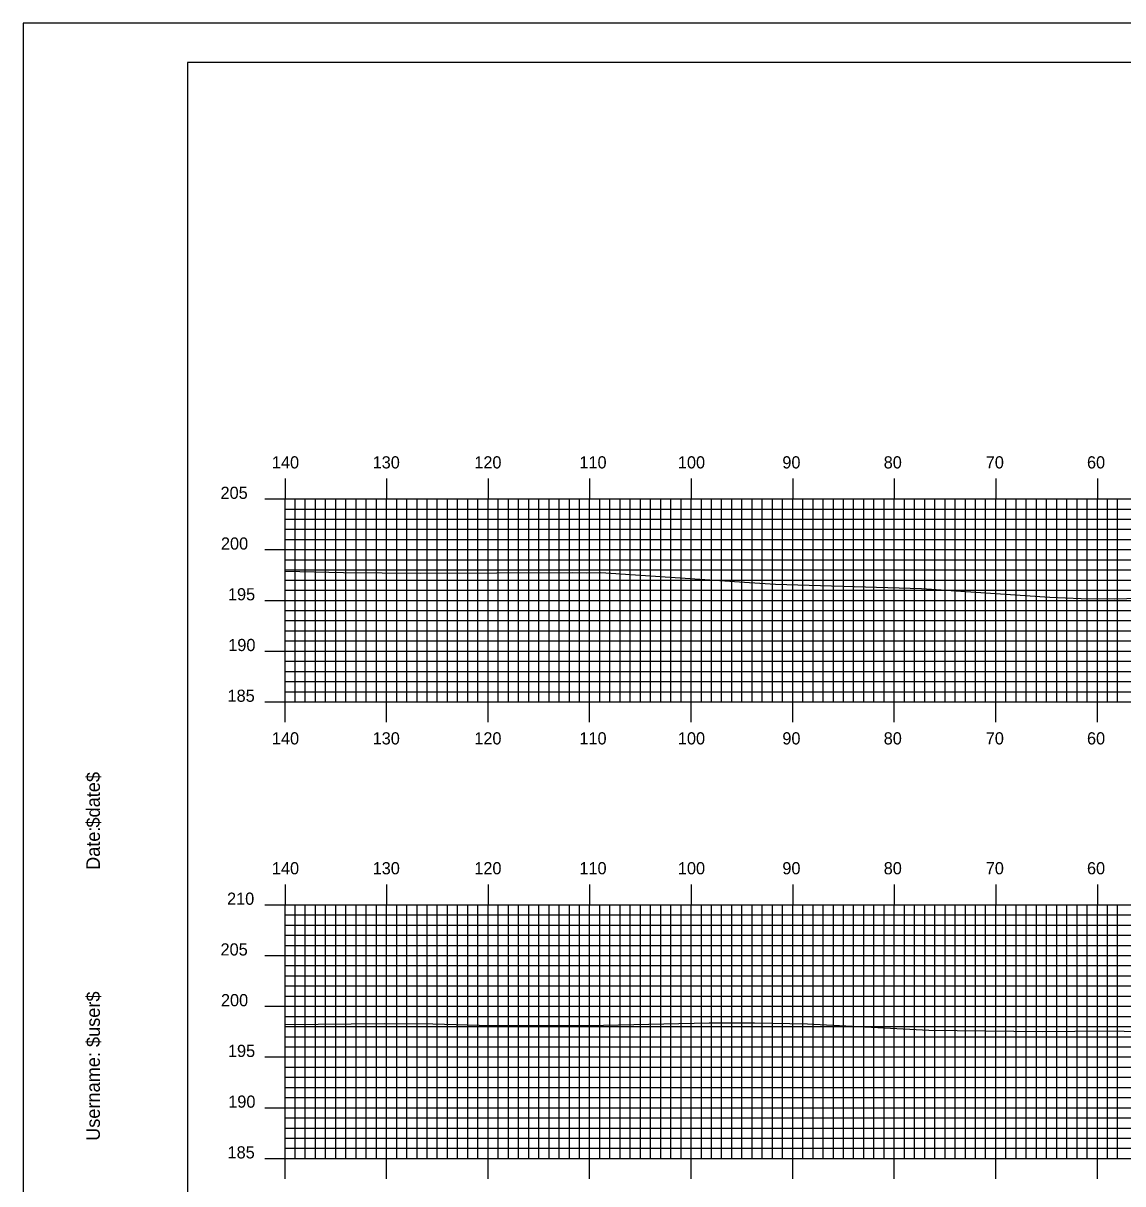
# Model space of a CAD drawing. Extents: x 1814128 to 1814471, y 442591 to 442811.
# Drawn here: x 1814128.2 to 1814236.5, y 442696.2 to 442810.5 of the extents above; entities that cross this region are included whole.
import ezdxf

# ---------------------------------------------------------------- set-up
doc = ezdxf.new("R2010")
doc.units = 0
for name, color, linetype in [('BORDER', 7, 'Continuous'), ('H_V ANNOTATION', 7, 'Continuous'), ('MAJOR', 7, 'Continuous'), ('MINOR', 7, 'Continuous'), ('PLOT BOUNDARY', 7, 'Continuous'), ('S_Roadway_Centerline', 7, 'Continuous')]:
    doc.layers.add(name, color=color, linetype=linetype)

msp = doc.modelspace()

# ---------------------------------------------------------------- linework, layer by layer
at = {"layer": 'BORDER'}
msp.add_lwpolyline([(1814144.39, 442596.67), (1814464.39, 442596.67), (1814464.39, 442806.67), (1814144.39, 442806.67)], close=True, dxfattribs=at)
at = {"layer": 'MAJOR'}
for p, q in [((1814153.99, 442765.67), (1814153.99, 442763.67)), ((1814163.99, 442765.67), (1814163.99, 442763.67)), ((1814173.99, 442765.67), (1814173.99, 442763.67)), ((1814183.99, 442765.67), (1814183.99, 442763.67)), ((1814193.99, 442765.67), (1814193.99, 442763.67)), ((1814203.99, 442765.67), (1814203.99, 442763.67)), ((1814213.99, 442765.67), (1814213.99, 442763.67)), ((1814223.99, 442765.67), (1814223.99, 442763.67)), ((1814233.99, 442765.67), (1814233.99, 442763.67)), ((1814151.99, 442763.67), (1814153.99, 442763.67)), ((1814153.99, 442763.67), (1814433.99, 442763.67)), ((1814153.99, 442743.67), (1814153.99, 442763.67)), ((1814153.99, 442743.67), (1814153.99, 442763.67)), ((1814153.99, 442763.67), (1814433.99, 442763.67)), ((1814163.99, 442743.67), (1814163.99, 442763.67)), ((1814173.99, 442743.67), (1814173.99, 442763.67)), ((1814183.99, 442743.67), (1814183.99, 442763.67)), ((1814193.99, 442743.67), (1814193.99, 442763.67)), ((1814203.99, 442743.67), (1814203.99, 442763.67)), ((1814213.99, 442743.67), (1814213.99, 442763.67)), ((1814223.99, 442743.67), (1814223.99, 442763.67)), ((1814233.99, 442743.67), (1814233.99, 442763.67)), ((1814151.99, 442758.67), (1814153.99, 442758.67)), ((1814153.99, 442758.67), (1814433.99, 442758.67)), ((1814151.99, 442753.67), (1814153.99, 442753.67)), ((1814153.99, 442753.67), (1814433.99, 442753.67)), ((1814151.99, 442748.67), (1814153.99, 442748.67)), ((1814153.99, 442748.67), (1814433.99, 442748.67)), ((1814151.99, 442743.67), (1814153.99, 442743.67)), ((1814153.99, 442743.67), (1814433.99, 442743.67)), ((1814153.99, 442743.67), (1814433.99, 442743.67)), ((1814153.99, 442741.66), (1814153.99, 442743.67)), ((1814163.99, 442741.66), (1814163.99, 442743.67)), ((1814173.99, 442741.66), (1814173.99, 442743.67)), ((1814183.99, 442741.66), (1814183.99, 442743.67)), ((1814193.99, 442741.66), (1814193.99, 442743.67)), ((1814203.99, 442741.66), (1814203.99, 442743.67)), ((1814213.99, 442741.66), (1814213.99, 442743.67)), ((1814223.99, 442741.66), (1814223.99, 442743.67)), ((1814233.99, 442741.66), (1814233.99, 442743.67)), ((1814153.99, 442725.67), (1814153.99, 442723.67)), ((1814163.99, 442725.67), (1814163.99, 442723.67)), ((1814173.99, 442725.67), (1814173.99, 442723.67)), ((1814183.99, 442725.67), (1814183.99, 442723.67)), ((1814193.99, 442725.67), (1814193.99, 442723.67)), ((1814203.99, 442725.67), (1814203.99, 442723.67)), ((1814213.99, 442725.67), (1814213.99, 442723.67)), ((1814223.99, 442725.67), (1814223.99, 442723.67)), ((1814233.99, 442725.67), (1814233.99, 442723.67)), ((1814151.99, 442723.67), (1814153.99, 442723.67)), ((1814153.99, 442723.67), (1814433.99, 442723.67)), ((1814153.99, 442698.67), (1814153.99, 442723.67)), ((1814153.99, 442698.67), (1814153.99, 442723.67)), ((1814153.99, 442723.67), (1814433.99, 442723.67)), ((1814163.99, 442698.67), (1814163.99, 442723.67)), ((1814173.99, 442698.67), (1814173.99, 442723.67)), ((1814183.99, 442698.67), (1814183.99, 442723.67)), ((1814193.99, 442698.67), (1814193.99, 442723.67)), ((1814203.99, 442698.67), (1814203.99, 442723.67)), ((1814213.99, 442698.67), (1814213.99, 442723.67)), ((1814223.99, 442698.67), (1814223.99, 442723.67)), ((1814233.99, 442698.67), (1814233.99, 442723.67)), ((1814151.99, 442718.67), (1814153.99, 442718.67)), ((1814153.99, 442718.67), (1814433.99, 442718.67)), ((1814151.99, 442713.67), (1814153.99, 442713.67)), ((1814153.99, 442713.67), (1814433.99, 442713.67)), ((1814151.99, 442708.67), (1814153.99, 442708.67)), ((1814153.99, 442708.67), (1814433.99, 442708.67)), ((1814151.99, 442703.67), (1814153.99, 442703.67)), ((1814153.99, 442703.67), (1814433.99, 442703.67)), ((1814151.99, 442698.67), (1814153.99, 442698.67)), ((1814153.99, 442698.67), (1814433.99, 442698.67)), ((1814153.99, 442698.67), (1814433.99, 442698.67)), ((1814153.99, 442696.66), (1814153.99, 442698.67)), ((1814163.99, 442696.66), (1814163.99, 442698.67)), ((1814173.99, 442696.66), (1814173.99, 442698.67)), ((1814183.99, 442696.66), (1814183.99, 442698.67)), ((1814193.99, 442696.66), (1814193.99, 442698.67)), ((1814203.99, 442696.66), (1814203.99, 442698.67)), ((1814213.99, 442696.66), (1814213.99, 442698.67)), ((1814223.99, 442696.66), (1814223.99, 442698.67)), ((1814233.99, 442696.66), (1814233.99, 442698.67))]:
    msp.add_line(p, q, dxfattribs=at)
at = {"layer": 'MINOR'}
for p, q in [((1814154.99, 442743.67), (1814154.99, 442763.67)), ((1814155.99, 442743.67), (1814155.99, 442763.67)), ((1814156.99, 442743.67), (1814156.99, 442763.67)), ((1814157.99, 442743.67), (1814157.99, 442763.67)), ((1814158.99, 442743.67), (1814158.99, 442763.67)), ((1814159.99, 442743.67), (1814159.99, 442763.67)), ((1814160.99, 442743.67), (1814160.99, 442763.67)), ((1814161.99, 442743.67), (1814161.99, 442763.67)), ((1814162.99, 442743.67), (1814162.99, 442763.67)), ((1814164.99, 442743.67), (1814164.99, 442763.67)), ((1814165.99, 442743.67), (1814165.99, 442763.67)), ((1814166.99, 442743.67), (1814166.99, 442763.67)), ((1814167.99, 442743.67), (1814167.99, 442763.67)), ((1814168.99, 442743.67), (1814168.99, 442763.67)), ((1814169.99, 442743.67), (1814169.99, 442763.67)), ((1814170.99, 442743.67), (1814170.99, 442763.67)), ((1814171.99, 442743.67), (1814171.99, 442763.67)), ((1814172.99, 442743.67), (1814172.99, 442763.67)), ((1814174.99, 442743.67), (1814174.99, 442763.67)), ((1814175.99, 442743.67), (1814175.99, 442763.67)), ((1814176.99, 442743.67), (1814176.99, 442763.67)), ((1814177.99, 442743.67), (1814177.99, 442763.67)), ((1814178.99, 442743.67), (1814178.99, 442763.67)), ((1814179.99, 442743.67), (1814179.99, 442763.67)), ((1814180.99, 442743.67), (1814180.99, 442763.67)), ((1814181.99, 442743.67), (1814181.99, 442763.67)), ((1814182.99, 442743.67), (1814182.99, 442763.67)), ((1814184.99, 442743.67), (1814184.99, 442763.67)), ((1814185.99, 442743.67), (1814185.99, 442763.67)), ((1814186.99, 442743.67), (1814186.99, 442763.67)), ((1814187.99, 442743.67), (1814187.99, 442763.67)), ((1814188.99, 442743.67), (1814188.99, 442763.67)), ((1814189.99, 442743.67), (1814189.99, 442763.67)), ((1814190.99, 442743.67), (1814190.99, 442763.67)), ((1814191.99, 442743.67), (1814191.99, 442763.67)), ((1814192.99, 442743.67), (1814192.99, 442763.67)), ((1814194.99, 442743.67), (1814194.99, 442763.67)), ((1814195.99, 442743.67), (1814195.99, 442763.67)), ((1814196.99, 442743.67), (1814196.99, 442763.67)), ((1814197.99, 442743.67), (1814197.99, 442763.67)), ((1814198.99, 442743.67), (1814198.99, 442763.67)), ((1814199.99, 442743.67), (1814199.99, 442763.67)), ((1814200.99, 442743.67), (1814200.99, 442763.67)), ((1814201.99, 442743.67), (1814201.99, 442763.67)), ((1814202.99, 442743.67), (1814202.99, 442763.67)), ((1814204.99, 442743.67), (1814204.99, 442763.67)), ((1814205.99, 442743.67), (1814205.99, 442763.67)), ((1814206.99, 442743.67), (1814206.99, 442763.67)), ((1814207.99, 442743.67), (1814207.99, 442763.67)), ((1814208.99, 442743.67), (1814208.99, 442763.67)), ((1814209.99, 442743.67), (1814209.99, 442763.67)), ((1814210.99, 442743.67), (1814210.99, 442763.67)), ((1814211.99, 442743.67), (1814211.99, 442763.67)), ((1814212.99, 442743.67), (1814212.99, 442763.67)), ((1814214.99, 442743.67), (1814214.99, 442763.67)), ((1814215.99, 442743.67), (1814215.99, 442763.67)), ((1814216.99, 442743.67), (1814216.99, 442763.67)), ((1814217.99, 442743.67), (1814217.99, 442763.67)), ((1814218.99, 442743.67), (1814218.99, 442763.67)), ((1814219.99, 442743.67), (1814219.99, 442763.67)), ((1814220.99, 442743.67), (1814220.99, 442763.67)), ((1814221.99, 442743.67), (1814221.99, 442763.67)), ((1814222.99, 442743.67), (1814222.99, 442763.67)), ((1814224.99, 442743.67), (1814224.99, 442763.67)), ((1814225.99, 442743.67), (1814225.99, 442763.67)), ((1814226.99, 442743.67), (1814226.99, 442763.67)), ((1814227.99, 442743.67), (1814227.99, 442763.67)), ((1814228.99, 442743.67), (1814228.99, 442763.67)), ((1814229.99, 442743.67), (1814229.99, 442763.67)), ((1814230.99, 442743.67), (1814230.99, 442763.67)), ((1814231.99, 442743.67), (1814231.99, 442763.67)), ((1814232.99, 442743.67), (1814232.99, 442763.67)), ((1814234.99, 442743.67), (1814234.99, 442763.67)), ((1814235.99, 442743.67), (1814235.99, 442763.67)), ((1814153.99, 442762.67), (1814433.99, 442762.67)), ((1814153.99, 442762.67), (1814156, 442762.67)), ((1814153.99, 442761.67), (1814433.99, 442761.67)), ((1814153.99, 442761.67), (1814156, 442761.67)), ((1814153.99, 442760.67), (1814433.99, 442760.67)), ((1814153.99, 442760.67), (1814156, 442760.67)), ((1814153.99, 442759.67), (1814433.99, 442759.67)), ((1814153.99, 442759.67), (1814156, 442759.67)), ((1814153.99, 442757.67), (1814433.99, 442757.67)), ((1814153.99, 442757.67), (1814156, 442757.67)), ((1814153.99, 442756.67), (1814433.99, 442756.67)), ((1814153.99, 442756.67), (1814156, 442756.67)), ((1814153.99, 442755.67), (1814433.99, 442755.67)), ((1814153.99, 442755.67), (1814156, 442755.67)), ((1814153.99, 442754.67), (1814433.99, 442754.67)), ((1814153.99, 442754.67), (1814156, 442754.67)), ((1814153.99, 442752.67), (1814433.99, 442752.67)), ((1814153.99, 442752.67), (1814156, 442752.67)), ((1814153.99, 442751.67), (1814433.99, 442751.67)), ((1814153.99, 442751.67), (1814156, 442751.67)), ((1814153.99, 442750.67), (1814433.99, 442750.67)), ((1814153.99, 442750.67), (1814156, 442750.67)), ((1814153.99, 442749.67), (1814433.99, 442749.67)), ((1814153.99, 442749.67), (1814156, 442749.67)), ((1814153.99, 442747.67), (1814433.99, 442747.67)), ((1814153.99, 442747.67), (1814156, 442747.67)), ((1814153.99, 442746.67), (1814433.99, 442746.67)), ((1814153.99, 442746.67), (1814156, 442746.67)), ((1814153.99, 442745.67), (1814433.99, 442745.67)), ((1814153.99, 442745.67), (1814156, 442745.67)), ((1814153.99, 442744.67), (1814433.99, 442744.67)), ((1814153.99, 442744.67), (1814156, 442744.67)), ((1814154.99, 442698.67), (1814154.99, 442723.67)), ((1814155.99, 442698.67), (1814155.99, 442723.67)), ((1814156.99, 442698.67), (1814156.99, 442723.67)), ((1814157.99, 442698.67), (1814157.99, 442723.67)), ((1814158.99, 442698.67), (1814158.99, 442723.67)), ((1814159.99, 442698.67), (1814159.99, 442723.67)), ((1814160.99, 442698.67), (1814160.99, 442723.67)), ((1814161.99, 442698.67), (1814161.99, 442723.67)), ((1814162.99, 442698.67), (1814162.99, 442723.67)), ((1814164.99, 442698.67), (1814164.99, 442723.67)), ((1814165.99, 442698.67), (1814165.99, 442723.67)), ((1814166.99, 442698.67), (1814166.99, 442723.67)), ((1814167.99, 442698.67), (1814167.99, 442723.67)), ((1814168.99, 442698.67), (1814168.99, 442723.67)), ((1814169.99, 442698.67), (1814169.99, 442723.67)), ((1814170.99, 442698.67), (1814170.99, 442723.67)), ((1814171.99, 442698.67), (1814171.99, 442723.67)), ((1814172.99, 442698.67), (1814172.99, 442723.67)), ((1814174.99, 442698.67), (1814174.99, 442723.67)), ((1814175.99, 442698.67), (1814175.99, 442723.67)), ((1814176.99, 442698.67), (1814176.99, 442723.67)), ((1814177.99, 442698.67), (1814177.99, 442723.67)), ((1814178.99, 442698.67), (1814178.99, 442723.67)), ((1814179.99, 442698.67), (1814179.99, 442723.67)), ((1814180.99, 442698.67), (1814180.99, 442723.67)), ((1814181.99, 442698.67), (1814181.99, 442723.67)), ((1814182.99, 442698.67), (1814182.99, 442723.67)), ((1814184.99, 442698.67), (1814184.99, 442723.67)), ((1814185.99, 442698.67), (1814185.99, 442723.67)), ((1814186.99, 442698.67), (1814186.99, 442723.67)), ((1814187.99, 442698.67), (1814187.99, 442723.67)), ((1814188.99, 442698.67), (1814188.99, 442723.67)), ((1814189.99, 442698.67), (1814189.99, 442723.67)), ((1814190.99, 442698.67), (1814190.99, 442723.67)), ((1814191.99, 442698.67), (1814191.99, 442723.67)), ((1814192.99, 442698.67), (1814192.99, 442723.67)), ((1814194.99, 442698.67), (1814194.99, 442723.67)), ((1814195.99, 442698.67), (1814195.99, 442723.67)), ((1814196.99, 442698.67), (1814196.99, 442723.67)), ((1814197.99, 442698.67), (1814197.99, 442723.67)), ((1814198.99, 442698.67), (1814198.99, 442723.67)), ((1814199.99, 442698.67), (1814199.99, 442723.67)), ((1814200.99, 442698.67), (1814200.99, 442723.67)), ((1814201.99, 442698.67), (1814201.99, 442723.67)), ((1814202.99, 442698.67), (1814202.99, 442723.67)), ((1814204.99, 442698.67), (1814204.99, 442723.67)), ((1814205.99, 442698.67), (1814205.99, 442723.67)), ((1814206.99, 442698.67), (1814206.99, 442723.67)), ((1814207.99, 442698.67), (1814207.99, 442723.67)), ((1814208.99, 442698.67), (1814208.99, 442723.67)), ((1814209.99, 442698.67), (1814209.99, 442723.67)), ((1814210.99, 442698.67), (1814210.99, 442723.67)), ((1814211.99, 442698.67), (1814211.99, 442723.67)), ((1814212.99, 442698.67), (1814212.99, 442723.67)), ((1814214.99, 442698.67), (1814214.99, 442723.67)), ((1814215.99, 442698.67), (1814215.99, 442723.67)), ((1814216.99, 442698.67), (1814216.99, 442723.67)), ((1814217.99, 442698.67), (1814217.99, 442723.67)), ((1814218.99, 442698.67), (1814218.99, 442723.67)), ((1814219.99, 442698.67), (1814219.99, 442723.67)), ((1814220.99, 442698.67), (1814220.99, 442723.67)), ((1814221.99, 442698.67), (1814221.99, 442723.67)), ((1814222.99, 442698.67), (1814222.99, 442723.67)), ((1814224.99, 442698.67), (1814224.99, 442723.67)), ((1814225.99, 442698.67), (1814225.99, 442723.67)), ((1814226.99, 442698.67), (1814226.99, 442723.67)), ((1814227.99, 442698.67), (1814227.99, 442723.67)), ((1814228.99, 442698.67), (1814228.99, 442723.67)), ((1814229.99, 442698.67), (1814229.99, 442723.67)), ((1814230.99, 442698.67), (1814230.99, 442723.67)), ((1814231.99, 442698.67), (1814231.99, 442723.67)), ((1814232.99, 442698.67), (1814232.99, 442723.67)), ((1814234.99, 442698.67), (1814234.99, 442723.67)), ((1814235.99, 442698.67), (1814235.99, 442723.67)), ((1814153.99, 442722.67), (1814433.99, 442722.67)), ((1814153.99, 442722.67), (1814156, 442722.67)), ((1814153.99, 442721.67), (1814433.99, 442721.67)), ((1814153.99, 442721.67), (1814156, 442721.67)), ((1814153.99, 442720.67), (1814433.99, 442720.67)), ((1814153.99, 442720.67), (1814156, 442720.67)), ((1814153.99, 442719.67), (1814433.99, 442719.67)), ((1814153.99, 442719.67), (1814156, 442719.67)), ((1814153.99, 442717.67), (1814433.99, 442717.67)), ((1814153.99, 442717.67), (1814156, 442717.67)), ((1814153.99, 442716.67), (1814433.99, 442716.67)), ((1814153.99, 442716.67), (1814156, 442716.67)), ((1814153.99, 442715.67), (1814433.99, 442715.67)), ((1814153.99, 442715.67), (1814156, 442715.67)), ((1814153.99, 442714.67), (1814433.99, 442714.67)), ((1814153.99, 442714.67), (1814156, 442714.67)), ((1814153.99, 442712.67), (1814433.99, 442712.67)), ((1814153.99, 442712.67), (1814156, 442712.67)), ((1814153.99, 442711.67), (1814433.99, 442711.67)), ((1814153.99, 442711.67), (1814156, 442711.67)), ((1814153.99, 442710.67), (1814433.99, 442710.67)), ((1814153.99, 442710.67), (1814156, 442710.67)), ((1814153.99, 442709.67), (1814433.99, 442709.67)), ((1814153.99, 442709.67), (1814156, 442709.67)), ((1814153.99, 442707.67), (1814433.99, 442707.67)), ((1814153.99, 442707.67), (1814156, 442707.67)), ((1814153.99, 442706.67), (1814433.99, 442706.67)), ((1814153.99, 442706.67), (1814156, 442706.67)), ((1814153.99, 442705.67), (1814433.99, 442705.67)), ((1814153.99, 442705.67), (1814156, 442705.67)), ((1814153.99, 442704.67), (1814433.99, 442704.67)), ((1814153.99, 442704.67), (1814156, 442704.67)), ((1814153.99, 442702.67), (1814433.99, 442702.67)), ((1814153.99, 442702.67), (1814156, 442702.67)), ((1814153.99, 442701.67), (1814433.99, 442701.67)), ((1814153.99, 442701.67), (1814156, 442701.67)), ((1814153.99, 442700.67), (1814433.99, 442700.67)), ((1814153.99, 442700.67), (1814156, 442700.67)), ((1814153.99, 442699.67), (1814433.99, 442699.67)), ((1814153.99, 442699.67), (1814156, 442699.67))]:
    msp.add_line(p, q, dxfattribs=at)
at = {"layer": 'PLOT BOUNDARY'}
msp.add_lwpolyline([(1814128.21, 442590.55), (1814468.21, 442590.55), (1814468.21, 442810.55), (1814128.21, 442810.55)], close=True, dxfattribs=at)
at = {"layer": 'S_Roadway_Centerline'}
for points in [[(1814153.99, 442756.55), (1814159.74, 442756.4), (1814167.36, 442756.36), (1814182.33, 442756.41), (1814183.68, 442756.38), (1814185.1, 442756.41), (1814199.73, 442755.43), (1814202.3, 442755.27), (1814216.68, 442754.85), (1814229.31, 442753.99), (1814232.4, 442753.86), (1814235.66, 442753.82), (1814249.38, 442754.17)], [(1814153.99, 442711.86), (1814163.74, 442711.96), (1814168.55, 442711.95), (1814174.26, 442711.78), (1814185.34, 442711.81), (1814195.77, 442712.03), (1814200.21, 442712.02), (1814205.46, 442711.93), (1814217.38, 442711.3), (1814228.57, 442711.18), (1814234.98, 442711.24), (1814239.96, 442711.14)]]:
    msp.add_lwpolyline(points, dxfattribs=at)

# ---------------------------------------------------------------- texts
at = {"layer": 'BORDER'}
for s, p in [('$date$', (1814135.76, 442731.28)), ('Date:', (1814135.76, 442727.1)), ('$user$', (1814135.76, 442709.65)), ('Username:', (1814135.76, 442700.4))]:
    msp.add_text(s, height=1.339, rotation=90, dxfattribs=at).set_placement(p)
at = {"layer": 'H_V ANNOTATION'}
for s, p in [('140', (1814152.7, 442766.67)), ('130', (1814162.62, 442766.67)), ('120', (1814172.63, 442766.67)), ('110', (1814182.98, 442766.67)), ('100', (1814192.68, 442766.67)), ('90', (1814202.97, 442766.67)), ('80', (1814212.95, 442766.67)), ('70', (1814223, 442766.67)), ('60', (1814232.97, 442766.67)), ('205', (1814147.64, 442763.67)), ('200', (1814147.68, 442758.67)), ('195', (1814148.37, 442753.67)), ('190', (1814148.4, 442748.67)), ('185', (1814148.33, 442743.67)), ('140', (1814152.7, 442739.47)), ('130', (1814162.62, 442739.47)), ('120', (1814172.63, 442739.47)), ('110', (1814182.98, 442739.47)), ('100', (1814192.68, 442739.47)), ('90', (1814202.97, 442739.47)), ('80', (1814212.95, 442739.47)), ('70', (1814223, 442739.47)), ('60', (1814232.97, 442739.47)), ('140', (1814152.7, 442726.67)), ('130', (1814162.62, 442726.67)), ('120', (1814172.63, 442726.67)), ('110', (1814182.98, 442726.67)), ('100', (1814192.68, 442726.67)), ('90', (1814202.97, 442726.67)), ('80', (1814212.95, 442726.67)), ('70', (1814223, 442726.67)), ('60', (1814232.97, 442726.67)), ('210', (1814148.28, 442723.67)), ('205', (1814147.64, 442718.67)), ('200', (1814147.68, 442713.67)), ('195', (1814148.37, 442708.67)), ('190', (1814148.4, 442703.67)), ('185', (1814148.33, 442698.67))]:
    msp.add_text(s, height=1.2, dxfattribs=at).set_placement(p)
at = {"layer": 'MAJOR'}
for p in [(1814153.99, 442743.67), (1814153.99, 442698.67)]:
    msp.add_text('-', height=0.012, dxfattribs=at).set_placement(p)

doc.saveas('drawing.dxf')
